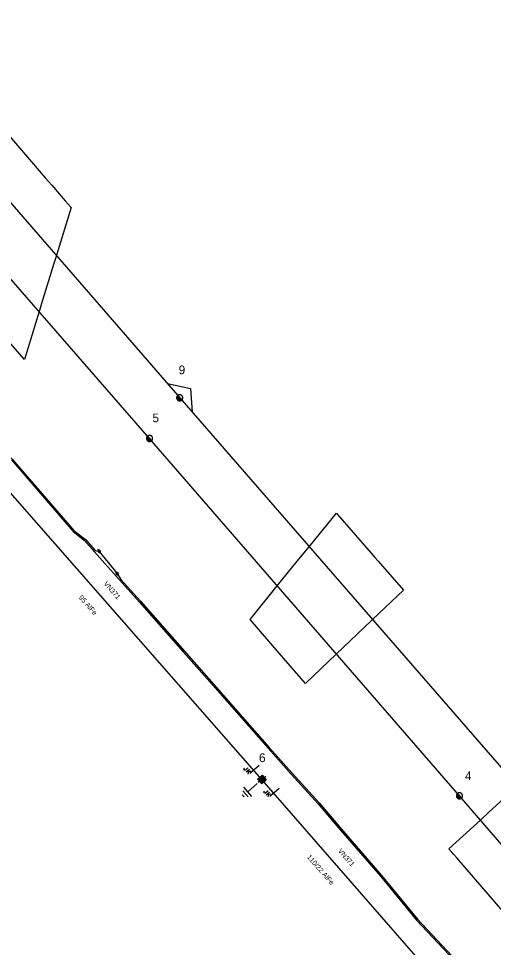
# Model space of a CAD drawing. Extents: x -540879 to -537255, y -1184046 to -1180016.
# Drawn here: x -537657.8 to -537563.1, y -1180339.5 to -1180154.3 of the extents above; entities that cross this region are included whole.
import ezdxf

# ---------------------------------------------------------------- set-up
doc = ezdxf.new("R2010")
doc.units = 0
for name, color, linetype in [('Vrstva 1', 7, 'Continuous'), ('Vrstva 13', 7, 'Continuous'), ('Vrstva 14', 7, 'Continuous'), ('Vrstva 15', 7, 'Continuous'), ('Vrstva 18', 7, 'Continuous'), ('Vrstva 19', 7, 'Continuous'), ('Vrstva 2', 7, 'Continuous'), ('Vrstva 3', 7, 'Continuous'), ('Vrstva 35', 7, 'Continuous'), ('Vrstva 4', 7, 'Continuous'), ('Vrstva 5', 7, 'Continuous')]:
    doc.layers.add(name, color=color, linetype=linetype)

# ---------------------------------------------------------------- blocks, each defined once
blk = doc.blocks.new('VN840')
at = {"layer": 'Vrstva 15'}
for points in [[(-0.01, 1.41), (-0.01, -1.09)], [(-1.51, -1.24), (-1.51, -1.15)], [(-1.48, -1.35), (-1.51, -1.24)], [(-1.33, -1.42), (-1.48, -1.35)], [(-1.27, -1.42), (-1.33, -1.42)], [(-1.13, -1.35), (-1.27, -1.42)], [(-1.09, -1.24), (-1.13, -1.35)], [(-1.09, -0.59), (-1.09, -1.24)], [(-0.68, -0.59), (-0.68, -1.42)], [(-0.68, -1.11), (-0.27, -0.59)], [(-0.54, -0.94), (-0.2, -1.42)]]:
    blk.add_lwpolyline(points, dxfattribs=at)
blk = doc.blocks.new('VN860')
at = {"layer": 'Vrstva 15'}
for points in [[(-3.74, 0), (0.01, 2.82)], [(0.01, 2.82), (3.76, 0)]]:
    blk.add_lwpolyline(points, dxfattribs=at)
blk = doc.blocks.new('VN440')
at = {"layer": 'Vrstva 2'}
for points in [[(1.22, 0), (1.21, 0.13), (1.19, 0.25), (1.16, 0.38), (1.11, 0.5), (1.05, 0.61), (0.98, 0.72), (0.9, 0.82), (0.81, 0.91), (0.71, 0.99), (0.6, 1.06), (0.49, 1.12), (0.37, 1.16), (0.25, 1.2), (0.12, 1.22), (-0.01, 1.22), (-0.14, 1.22), (-0.26, 1.2), (-0.39, 1.16), (-0.51, 1.12), (-0.62, 1.06), (-0.73, 0.99), (-0.83, 0.91), (-0.92, 0.82), (-1, 0.72), (-1.07, 0.61), (-1.13, 0.5), (-1.18, 0.38), (-1.21, 0.25), (-1.23, 0.13), (-1.24, 0), (-1.23, -0.13), (-1.21, -0.26), (-1.18, -0.38), (-1.13, -0.5), (-1.07, -0.62), (-1, -0.73), (-0.92, -0.83), (-0.83, -0.92), (-0.73, -1), (-0.62, -1.07), (-0.51, -1.13), (-0.39, -1.17), (-0.26, -1.2), (-0.14, -1.23), (-0.01, -1.23), (0.12, -1.23), (0.25, -1.2), (0.37, -1.17), (0.49, -1.13), (0.6, -1.07), (0.71, -1), (0.81, -0.92), (0.9, -0.83), (0.98, -0.73), (1.05, -0.62), (1.11, -0.5), (1.16, -0.38), (1.19, -0.26), (1.21, -0.13), (1.22, 0)], [(-1.24, 0), (1.22, 0)], [(-1.18, -0.34), (1.1, -0.34)], [(-1.01, -0.63), (0.97, -0.63)], [(-0.74, -0.92), (0.68, -0.92)]]:
    blk.add_lwpolyline(points, dxfattribs=at)
blk = doc.blocks.new('VN870')
at = {"layer": 'Vrstva 4'}
for points in [[(0, -0.25), (0.5, 0), (0, 0.25), (-0.5, 0), (0, -0.25)], [(0.37, 0), (0, 0.19), (-0.36, 0), (0, -0.19), (0.37, 0)], [(0.24, 0), (0, 0.12), (-0.25, 0), (0, -0.12), (0.24, 0)], [(0.12, 0), (0, 0.06), (-0.13, 0), (0, -0.06), (0.12, 0)]]:
    blk.add_lwpolyline(points, dxfattribs=at)
blk = doc.blocks.new('VN810')
at = {"layer": 'Vrstva 14'}
for points in [[(0, -1.25), (0, -3.75)], [(1.25, -3.75), (-1.25, -3.75)], [(0.77, -4.37), (-0.8, -4.37)], [(0, -5), (-0.25, -5)], [(0.27, -5), (0, -5)]]:
    blk.add_lwpolyline(points, dxfattribs=at)
blk = doc.blocks.new('VN470')
at = {"layer": 'Vrstva 2'}
for points in [[(-1.23, 1.22), (1.23, 1.22)], [(-1.23, -1.23), (-1.23, 1.22)], [(-0.92, 0.9), (0.92, 0.9)], [(-0.92, -0.95), (-0.92, 0.9)], [(-0.61, 0.61), (0.61, 0.61)], [(-0.61, -0.62), (-0.61, 0.61)], [(-0.31, -0.27), (-0.31, 0.34)], [(-0.31, 0.34), (0.31, 0.34)], [(0, 1.22), (0, 1.97)], [(0.31, 0.34), (0.31, -0.27)], [(0.61, 0.61), (0.61, -0.62)], [(0.92, 0.9), (0.92, -0.95)], [(1.23, 1.22), (1.23, -1.23)], [(1.23, -1.23), (-1.23, -1.23)], [(0.92, -0.95), (-0.92, -0.95)], [(0.61, -0.62), (-0.61, -0.62)], [(0.31, -0.27), (-0.31, -0.27)], [(0, -1.23), (0, -1.98)]]:
    blk.add_lwpolyline(points, dxfattribs=at)

msp = doc.modelspace()

# ---------------------------------------------------------------- linework, layer by layer
at = {"layer": 'Vrstva 1'}
for points in [[(-537534.01, -1180350.75), (-537569.87, -1180309.27), (-537631.69, -1180238), (-537723.88, -1180132.14), (-537744.24, -1180108.87)], [(-537716.13, -1180125.67), (-537714.92, -1180127.04), (-537625.68, -1180229.9), (-537553.13, -1180313.31), (-537526.37, -1180344.35)], [(-537609.27, -1180305.98), (-537675.17, -1180231.02), (-537716.9, -1180183.95)], [(-537499.2, -1180431.55), (-537543.96, -1180380.85), (-537574.08, -1180346.4), (-537609.27, -1180305.98)]]:
    msp.add_lwpolyline(points, dxfattribs=at)
at = {"layer": 'Vrstva 35'}
msp.add_lwpolyline([(-537687.5, -1180145.67), (-537679.68, -1180154.68), (-537672.9, -1180162.5), (-537668.74, -1180167.29), (-537668.07, -1180168.07), (-537662.5, -1180174.49), (-537656.46, -1180181.46), (-537652.52, -1180186), (-537651.21, -1180187.5), (-537648.53, -1180190.59), (-537647.35, -1180191.95), (-537649.74, -1180199.74), (-537650.29, -1180201.53), (-537650.78, -1180203.13), (-537653.23, -1180211.11), (-537653.66, -1180212.5), (-537653.72, -1180212.7), (-537656.66, -1180222.27), (-537708.11, -1180163.2), (-537707.97, -1180162.5), (-537706.82, -1180156.82), (-537705.99, -1180152.69)], dxfattribs=at)
for points in [[(-537594.18, -1180253.17), (-537587.5, -1180260.85), (-537586.73, -1180261.73), (-537586.06, -1180262.5), (-537581.05, -1180268.26), (-537587.21, -1180274.12), (-537587.5, -1180274.4), (-537594.41, -1180280.98), (-537600.57, -1180286.85), (-537605.81, -1180280.81), (-537611.65, -1180274.07), (-537606.21, -1180267.38), (-537602.24, -1180262.5), (-537599.86, -1180259.58), (-537594.42, -1180252.89)], [(-537551.84, -1180301.84), (-537546.7, -1180307.75), (-537542.6, -1180312.5), (-537540.24, -1180315.24), (-537537.51, -1180318.41), (-537533.57, -1180322.97), (-537537.5, -1180327.4), (-537539.27, -1180329.39), (-537544.04, -1180334.78), (-537547.75, -1180334.86), (-537558.79, -1180335.09), (-537559.39, -1180334.39), (-537562.49, -1180330.8), (-537570.41, -1180321.64), (-537570.98, -1180320.98), (-537571.43, -1180320.46), (-537571.96, -1180319.85), (-537565.7, -1180314.09), (-537563.98, -1180312.5), (-537562.5, -1180311.13), (-537558.35, -1180307.31), (-537552.1, -1180301.55)]]:
    msp.add_lwpolyline(points, close=True, dxfattribs=at)
at = {"layer": 'Vrstva 5'}
for points in [[(-537664.23, -1180235.35), (-537663.94, -1180237.31), (-537662.65, -1180238.85), (-537659.09, -1180242.11), (-537646.78, -1180256.35), (-537644.49, -1180258.15), (-537642.58, -1180260.31), (-537641.72, -1180260.52)], [(-537659.27, -1180242.28), (-537646.96, -1180256.53), (-537644.67, -1180258.33), (-537640.61, -1180262.92), (-537633.71, -1180270.63), (-537625, -1180280.53), (-537618.6, -1180287.74), (-537611.91, -1180295.34), (-537608.05, -1180299.76), (-537603.42, -1180304.94), (-537598.08, -1180310.85), (-537593.62, -1180316.1), (-537585.59, -1180325.32), (-537578.44, -1180334.06), (-537567.62, -1180345.54)], [(-537641.72, -1180260.52), (-537638.14, -1180264.96)], [(-537638.14, -1180264.96), (-537637.43, -1180266.1), (-537633.52, -1180270.46), (-537624.81, -1180280.36), (-537618.41, -1180287.57), (-537611.73, -1180295.17), (-537607.87, -1180299.6), (-537603.23, -1180304.77), (-537597.89, -1180310.68), (-537593.43, -1180315.94), (-537585.4, -1180325.16), (-537578.25, -1180333.89), (-537567.44, -1180345.37)]]:
    msp.add_lwpolyline(points, dxfattribs=at)

# ---------------------------------------------------------------- block references
at = {"layer": 'Vrstva 13', "yscale": 0.5}
for name, p, xscale, rotation in [('VN440', (-537625.68, -1180229.9), 0.5000000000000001, -48.882733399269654), ('VN440', (-537631.69, -1180238), 0.5, -48.952333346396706), ('VN470', (-537609.27, -1180305.98), 0.5, -49.03789719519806), ('VN440', (-537569.87, -1180309.27), 0.5, -49.156158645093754)]:
    msp.add_blockref(name, p, dxfattribs=dict(at, xscale=xscale, rotation=rotation))
at = {"layer": 'Vrstva 15', "rotation": -48.72875557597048}
msp.add_blockref('VN810', (-537609.27, -1180305.98), dxfattribs=at)
at = {"layer": 'Vrstva 18'}
for name, p, rotation in [('VN860', (-537625.68, -1180229.9), -49.15608335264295), ('VN840', (-537610.9, -1180304.13), -48.670602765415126), ('VN840', (-537606.9, -1180308.71), -48.95688887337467)]:
    msp.add_blockref(name, p, dxfattribs=dict(at, rotation=rotation))
at = {"layer": 'Vrstva 19'}
for p, rotation in [((-537641.72, -1180260.52), -49.0486661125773), ((-537638.14, -1180264.96), 130.95133388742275)]:
    msp.add_blockref('VN870', p, dxfattribs=dict(at, rotation=rotation))

# ---------------------------------------------------------------- texts
at = {"layer": 'Vrstva 14'}
for s, p in [('9', (-537625.89, -1180225.2)), ('5', (-537631.12, -1180234.78)), ('6', (-537609.86, -1180302.54)), ('4', (-537568.77, -1180306.14))]:
    msp.add_text(s, height=1.75, dxfattribs=at).set_placement(p)
at = {"layer": 'Vrstva 2'}
for s, rotation, p in [('95 AlFe', 311.329, (-537645.91, -1180269.77)), ('110/22 AlFe', 311.043, (-537600.38, -1180321.51))]:
    msp.add_text(s, height=1, rotation=rotation, dxfattribs=at).set_placement(p)
at = {"layer": 'Vrstva 3'}
for rotation, p in [(311.329, (-537640.93, -1180267.02)), (311.043, (-537594.19, -1180320.3))]:
    msp.add_text('VN371', height=1, rotation=rotation, dxfattribs=at).set_placement(p)

doc.saveas('drawing.dxf')
